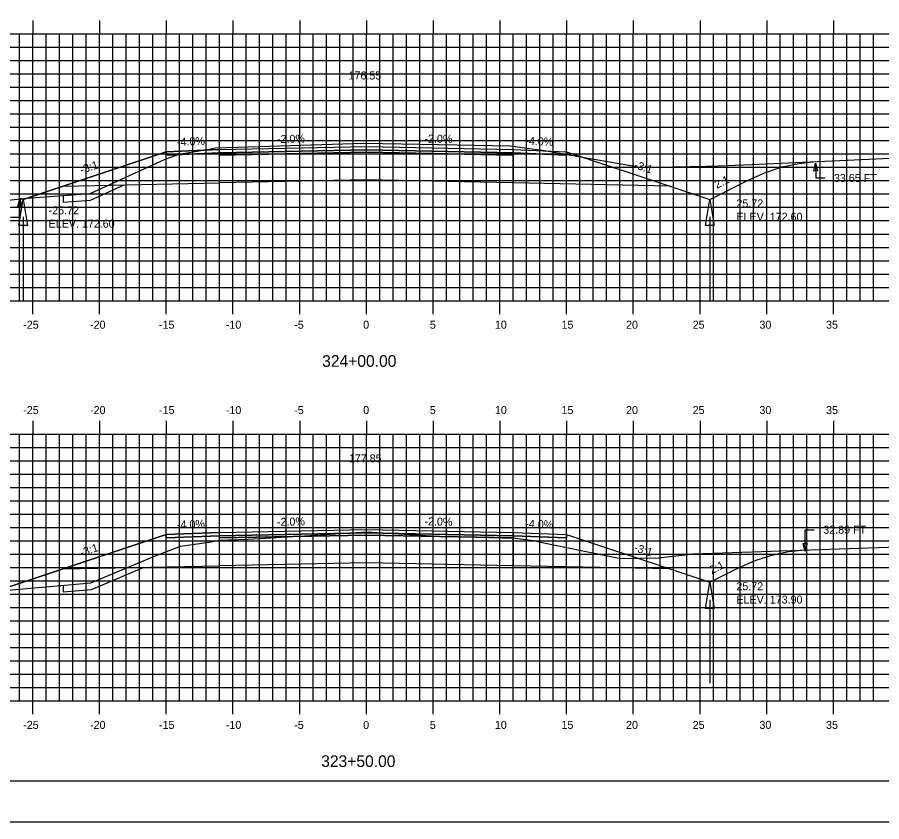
# Model space of a CAD drawing. Extents: x 1140315 to 1140485, y 608981 to 609091.
# Drawn here: x 1140372.3 to 1140437.1, y 608981.3 to 609041.6 of the extents above; entities that cross this region are included whole.
import ezdxf

# ---------------------------------------------------------------- set-up
doc = ezdxf.new("R2010")
doc.units = 0
for name, color, linetype in [('ANNOTATION', 7, 'Continuous'), ('BORDER', 7, 'Continuous'), ('D_Drainage_Ditch_Line', 7, 'Continuous'), ('D_Roadway_Centerline', 7, 'Continuous'), ('D_Roadway_Centerline_Text', 7, 'Continuous'), ('D_Roadway_Edge_Shoulder', 7, 'Continuous'), ('D_Roadway_Edge_TW', 7, 'Continuous'), ('D_Roadway_Pavement', 7, 'Continuous'), ('D_Roadway_SlopeLines', 7, 'Continuous'), ('D_Roadway_SubGrade', 7, 'Continuous'), ('D_Text_Standard', 7, 'Continuous'), ('H_V ANNOTATION', 7, 'Continuous'), ('MAJOR', 7, 'Continuous'), ('MINOR', 7, 'Continuous'), ('PLOT BOUNDARY', 7, 'Continuous'), ('S_Roadway_Centerline', 7, 'Continuous')]:
    doc.layers.add(name, color=color, linetype=linetype)

msp = doc.modelspace()

# ---------------------------------------------------------------- linework, layer by layer
for points in [[(1140372.532, 609027.976), (1140372.59, 609027.978), (1140372.648, 609027.971), (1140372.706, 609027.956), (1140372.763, 609027.931), (1140375.763, 609028.931), (1140383.487, 609031.506), (1140383.488, 609031.506), (1140387.488, 609031.666), (1140398.488, 609031.886), (1140409.488, 609031.666), (1140413.488, 609031.506), (1140421.211, 609028.931), (1140424.211, 609027.931), (1140427.134, 609029.392), (1140428.384, 609029.947), (1140429.634, 609030.359), (1140430.884, 609030.63), (1140432.134, 609030.759)], [(1140370.736, 608998.555), (1140372.763, 608999.23), (1140375.763, 609000.23), (1140383.487, 609002.805), (1140383.488, 609002.805), (1140387.488, 609002.965), (1140398.488, 609003.185), (1140409.488, 609002.965), (1140413.488, 609002.805), (1140421.211, 609000.23), (1140424.211, 608999.23), (1140426.373, 609000.311), (1140427.623, 609000.863), (1140428.873, 609001.27), (1140430.123, 609001.531), (1140431.373, 609001.646)]]:
    msp.add_lwpolyline(points)
at = {"layer": 'BORDER'}
msp.add_lwpolyline([(1140323.488, 608984.335), (1140483.488, 608984.335), (1140483.488, 609089.335), (1140323.488, 609089.335)], close=True, dxfattribs=at)
at = {"layer": 'D_Drainage_Ditch_Line'}
for p, q in [((1140372.763, 609026.619), (1140372.763, 609020.375)), ((1140424.212, 609026.619), (1140424.211, 609020.375)), ((1140424.212, 608997.918), (1140424.211, 608991.675))]:
    msp.add_line(p, q, dxfattribs=at)
for points in [[(1140373.091, 609025.963), (1140372.435, 609025.963), (1140372.763, 609027.931)], [(1140424.54, 609025.963), (1140423.883, 609025.963), (1140424.211, 609027.931)], [(1140424.54, 608997.262), (1140423.883, 608997.262), (1140424.211, 608999.23)]]:
    msp.add_lwpolyline(points, close=True, dxfattribs=at)
at = {"layer": 'D_Roadway_Edge_Shoulder'}
for points in [[(1140387.488, 609031.666), (1140383.488, 609031.506), (1140383.488, 609031.256), (1140387.488, 609031.416)], [(1140409.488, 609031.666), (1140413.488, 609031.506), (1140413.488, 609031.256), (1140409.488, 609031.416)], [(1140387.488, 609002.965), (1140383.488, 609002.805), (1140383.488, 609002.555), (1140387.488, 609002.715)], [(1140409.488, 609002.965), (1140413.488, 609002.805), (1140413.488, 609002.555), (1140409.488, 609002.715)]]:
    msp.add_lwpolyline(points, close=True, dxfattribs=at)
at = {"layer": 'D_Roadway_Edge_TW'}
for points in [[(1140387.488, 609031.416), (1140387.488, 609031.666), (1140398.488, 609031.886), (1140409.488, 609031.666), (1140409.488, 609031.416), (1140398.488, 609031.636)], [(1140387.488, 609002.715), (1140387.488, 609002.965), (1140398.488, 609003.185), (1140409.488, 609002.965), (1140409.488, 609002.715), (1140398.488, 609002.935)]]:
    msp.add_lwpolyline(points, close=True, dxfattribs=at)
at = {"layer": 'D_Roadway_Pavement'}
for points in [[(1140387.488, 609031.249), (1140387.488, 609031.416), (1140398.488, 609031.636), (1140409.488, 609031.416), (1140409.488, 609031.249), (1140398.488, 609031.469)], [(1140387.488, 609002.548), (1140387.488, 609002.715), (1140398.488, 609002.935), (1140409.488, 609002.715), (1140409.488, 609002.548), (1140398.488, 609002.768)]]:
    msp.add_lwpolyline(points, close=True, dxfattribs=at)
at = {"layer": 'D_Roadway_SlopeLines'}
for points in [[(1140424.211, 609027.931), (1140427.134, 609029.392), (1140428.384, 609029.947), (1140429.634, 609030.359), (1140430.884, 609030.63), (1140432.134, 609030.759)], [(1140375.763, 609028.931), (1140372.763, 609027.931)], [(1140375.763, 609028.228), (1140375.763, 609027.728), (1140377.819, 609027.877), (1140380.328, 609029.022)], [(1140421.211, 609028.931), (1140424.211, 609027.931)], [(1140372.763, 609027.931), (1140372.706, 609027.956), (1140372.648, 609027.971), (1140372.59, 609027.978), (1140372.532, 609027.976)], [(1140424.211, 608999.23), (1140426.373, 609000.311), (1140427.623, 609000.863), (1140428.873, 609001.27), (1140430.123, 609001.531), (1140431.373, 609001.646)], [(1140375.763, 609000.23), (1140372.763, 608999.23)], [(1140375.763, 608998.999), (1140375.763, 608998.499), (1140377.894, 608998.688), (1140381.835, 609000.352)], [(1140421.211, 609000.23), (1140424.211, 608999.23)], [(1140372.763, 608999.23), (1140370.736, 608998.555)]]:
    msp.add_lwpolyline(points, dxfattribs=at)
at = {"layer": 'D_Roadway_SubGrade'}
for points in [[(1140387.488, 609031.249), (1140387.488, 609031.416), (1140383.488, 609031.256), (1140383.488, 609031.506), (1140383.487, 609031.506), (1140375.763, 609028.931), (1140387.488, 609029.166)], [(1140409.488, 609031.249), (1140409.488, 609031.416), (1140413.488, 609031.256), (1140413.488, 609031.506), (1140413.488, 609031.506), (1140421.211, 609028.931), (1140409.488, 609029.166)], [(1140387.488, 609029.166), (1140387.488, 609031.249), (1140398.488, 609031.469), (1140409.488, 609031.249), (1140409.488, 609029.166), (1140398.488, 609029.386)], [(1140387.488, 609002.548), (1140387.488, 609002.715), (1140383.488, 609002.555), (1140383.488, 609002.805), (1140383.487, 609002.805), (1140375.763, 609000.23), (1140387.488, 609000.465)], [(1140387.488, 609000.465), (1140387.488, 609002.548), (1140398.488, 609002.768), (1140409.488, 609002.548), (1140409.488, 609000.465), (1140398.488, 609000.685)], [(1140409.488, 609002.548), (1140409.488, 609002.715), (1140413.488, 609002.555), (1140413.488, 609002.805), (1140413.488, 609002.805), (1140421.211, 609000.23), (1140409.488, 609000.465)]]:
    msp.add_lwpolyline(points, close=True, dxfattribs=at)
at = {"layer": 'D_Text_Standard'}
for points in [[(1140432.134, 609030.642), (1140432.292, 609030.063), (1140432.001, 609030.057)], [(1140372.532, 609027.976), (1140372.665, 609027.391), (1140372.374, 609027.397)], [(1140431.373, 609001.561), (1140431.223, 609002.142), (1140431.514, 609002.145)]]:
    msp.add_lwpolyline(points, close=True, dxfattribs=at)
for points in [[(1140432.134, 609030.642), (1140432.157, 609029.535), (1140432.837, 609029.535)], [(1140372.532, 609027.976), (1140372.501, 609026.568), (1140371.821, 609026.568)], [(1140431.373, 609001.561), (1140431.36, 609003.165), (1140432.04, 609003.165)]]:
    msp.add_lwpolyline(points, dxfattribs=at)
at = {"layer": 'MAJOR'}
for p, q in [((1140373.488, 609041.337), (1140373.488, 609040.335)), ((1140378.488, 609041.337), (1140378.488, 609040.335)), ((1140383.488, 609041.337), (1140383.488, 609040.335)), ((1140388.488, 609041.337), (1140388.488, 609040.335)), ((1140393.488, 609041.337), (1140393.488, 609040.335)), ((1140398.488, 609041.337), (1140398.488, 609040.335)), ((1140403.488, 609041.337), (1140403.488, 609040.335)), ((1140408.488, 609041.337), (1140408.488, 609040.335)), ((1140413.488, 609041.337), (1140413.488, 609040.335)), ((1140418.488, 609041.337), (1140418.488, 609040.335)), ((1140423.488, 609041.337), (1140423.488, 609040.335)), ((1140428.488, 609041.337), (1140428.488, 609040.335)), ((1140433.488, 609041.337), (1140433.488, 609040.335)), ((1140328.488, 609040.335), (1140468.488, 609040.335)), ((1140328.488, 609040.335), (1140468.488, 609040.335)), ((1140373.488, 609020.335), (1140373.488, 609040.335)), ((1140378.488, 609020.335), (1140378.488, 609040.335)), ((1140383.488, 609020.335), (1140383.488, 609040.335)), ((1140388.488, 609020.335), (1140388.488, 609040.335)), ((1140393.488, 609020.335), (1140393.488, 609040.335)), ((1140398.488, 609020.335), (1140398.488, 609040.335)), ((1140403.488, 609020.335), (1140403.488, 609040.335)), ((1140408.488, 609020.335), (1140408.488, 609040.335)), ((1140413.488, 609020.335), (1140413.488, 609040.335)), ((1140418.488, 609020.335), (1140418.488, 609040.335)), ((1140423.488, 609020.335), (1140423.488, 609040.335)), ((1140428.488, 609020.335), (1140428.488, 609040.335)), ((1140433.488, 609020.335), (1140433.488, 609040.335)), ((1140328.488, 609035.335), (1140468.488, 609035.335)), ((1140328.488, 609030.335), (1140468.488, 609030.335)), ((1140328.488, 609025.335), (1140468.488, 609025.335)), ((1140328.488, 609020.335), (1140468.488, 609020.335)), ((1140328.488, 609020.335), (1140468.488, 609020.335)), ((1140373.488, 609019.333), (1140373.488, 609020.335)), ((1140378.488, 609019.333), (1140378.488, 609020.335)), ((1140383.488, 609019.333), (1140383.488, 609020.335)), ((1140388.488, 609019.333), (1140388.488, 609020.335)), ((1140393.488, 609019.333), (1140393.488, 609020.335)), ((1140398.488, 609019.333), (1140398.488, 609020.335)), ((1140403.488, 609019.333), (1140403.488, 609020.335)), ((1140408.488, 609019.333), (1140408.488, 609020.335)), ((1140413.488, 609019.333), (1140413.488, 609020.335)), ((1140418.488, 609019.333), (1140418.488, 609020.335)), ((1140423.488, 609019.333), (1140423.488, 609020.335)), ((1140428.488, 609019.333), (1140428.488, 609020.335)), ((1140433.488, 609019.333), (1140433.488, 609020.335)), ((1140373.488, 609011.337), (1140373.488, 609010.335)), ((1140378.488, 609011.337), (1140378.488, 609010.335)), ((1140383.488, 609011.337), (1140383.488, 609010.335)), ((1140388.488, 609011.337), (1140388.488, 609010.335)), ((1140393.488, 609011.337), (1140393.488, 609010.335)), ((1140398.488, 609011.337), (1140398.488, 609010.335)), ((1140403.488, 609011.337), (1140403.488, 609010.335)), ((1140408.488, 609011.337), (1140408.488, 609010.335)), ((1140413.488, 609011.337), (1140413.488, 609010.335)), ((1140418.488, 609011.337), (1140418.488, 609010.335)), ((1140423.488, 609011.337), (1140423.488, 609010.335)), ((1140428.488, 609011.337), (1140428.488, 609010.335)), ((1140433.488, 609011.337), (1140433.488, 609010.335)), ((1140328.488, 609010.335), (1140468.488, 609010.335)), ((1140328.488, 609010.335), (1140468.488, 609010.335)), ((1140373.488, 608990.335), (1140373.488, 609010.335)), ((1140378.488, 608990.335), (1140378.488, 609010.335)), ((1140383.488, 608990.335), (1140383.488, 609010.335)), ((1140388.488, 608990.335), (1140388.488, 609010.335)), ((1140393.488, 608990.335), (1140393.488, 609010.335)), ((1140398.488, 608990.335), (1140398.488, 609010.335)), ((1140403.488, 608990.335), (1140403.488, 609010.335)), ((1140408.488, 608990.335), (1140408.488, 609010.335)), ((1140413.488, 608990.335), (1140413.488, 609010.335)), ((1140418.488, 608990.335), (1140418.488, 609010.335)), ((1140423.488, 608990.335), (1140423.488, 609010.335)), ((1140428.488, 608990.335), (1140428.488, 609010.335)), ((1140433.488, 608990.335), (1140433.488, 609010.335)), ((1140328.488, 609005.335), (1140468.488, 609005.335)), ((1140328.488, 609000.335), (1140468.488, 609000.335)), ((1140328.488, 608995.335), (1140468.488, 608995.335)), ((1140328.488, 608990.335), (1140468.488, 608990.335)), ((1140328.488, 608990.335), (1140468.488, 608990.335)), ((1140373.488, 608989.333), (1140373.488, 608990.335)), ((1140378.488, 608989.333), (1140378.488, 608990.335)), ((1140383.488, 608989.333), (1140383.488, 608990.335)), ((1140388.488, 608989.333), (1140388.488, 608990.335)), ((1140393.488, 608989.333), (1140393.488, 608990.335)), ((1140398.488, 608989.333), (1140398.488, 608990.335)), ((1140403.488, 608989.333), (1140403.488, 608990.335)), ((1140408.488, 608989.333), (1140408.488, 608990.335)), ((1140413.488, 608989.333), (1140413.488, 608990.335)), ((1140418.488, 608989.333), (1140418.488, 608990.335)), ((1140423.488, 608989.333), (1140423.488, 608990.335)), ((1140428.488, 608989.333), (1140428.488, 608990.335)), ((1140433.488, 608989.333), (1140433.488, 608990.335))]:
    msp.add_line(p, q, dxfattribs=at)
at = {"layer": 'MINOR'}
for p, q in [((1140372.488, 609020.335), (1140372.488, 609040.335)), ((1140374.488, 609020.335), (1140374.488, 609040.335)), ((1140375.488, 609020.335), (1140375.488, 609040.335)), ((1140376.488, 609020.335), (1140376.488, 609040.335)), ((1140377.488, 609020.335), (1140377.488, 609040.335)), ((1140379.488, 609020.335), (1140379.488, 609040.335)), ((1140380.488, 609020.335), (1140380.488, 609040.335)), ((1140381.488, 609020.335), (1140381.488, 609040.335)), ((1140382.488, 609020.335), (1140382.488, 609040.335)), ((1140384.488, 609020.335), (1140384.488, 609040.335)), ((1140385.488, 609020.335), (1140385.488, 609040.335)), ((1140386.488, 609020.335), (1140386.488, 609040.335)), ((1140387.488, 609020.335), (1140387.488, 609040.335)), ((1140389.488, 609020.335), (1140389.488, 609040.335)), ((1140390.488, 609020.335), (1140390.488, 609040.335)), ((1140391.488, 609020.335), (1140391.488, 609040.335)), ((1140392.488, 609020.335), (1140392.488, 609040.335)), ((1140394.488, 609020.335), (1140394.488, 609040.335)), ((1140395.488, 609020.335), (1140395.488, 609040.335)), ((1140396.488, 609020.335), (1140396.488, 609040.335)), ((1140397.488, 609020.335), (1140397.488, 609040.335)), ((1140399.488, 609020.335), (1140399.488, 609040.335)), ((1140400.488, 609020.335), (1140400.488, 609040.335)), ((1140401.488, 609020.335), (1140401.488, 609040.335)), ((1140402.488, 609020.335), (1140402.488, 609040.335)), ((1140404.488, 609020.335), (1140404.488, 609040.335)), ((1140405.488, 609020.335), (1140405.488, 609040.335)), ((1140406.488, 609020.335), (1140406.488, 609040.335)), ((1140407.488, 609020.335), (1140407.488, 609040.335)), ((1140409.488, 609020.335), (1140409.488, 609040.335)), ((1140410.488, 609020.335), (1140410.488, 609040.335)), ((1140411.488, 609020.335), (1140411.488, 609040.335)), ((1140412.488, 609020.335), (1140412.488, 609040.335)), ((1140414.488, 609020.335), (1140414.488, 609040.335)), ((1140415.488, 609020.335), (1140415.488, 609040.335)), ((1140416.488, 609020.335), (1140416.488, 609040.335)), ((1140417.488, 609020.335), (1140417.488, 609040.335)), ((1140419.488, 609020.335), (1140419.488, 609040.335)), ((1140420.488, 609020.335), (1140420.488, 609040.335)), ((1140421.488, 609020.335), (1140421.488, 609040.335)), ((1140422.488, 609020.335), (1140422.488, 609040.335)), ((1140424.488, 609020.335), (1140424.488, 609040.335)), ((1140425.488, 609020.335), (1140425.488, 609040.335)), ((1140426.488, 609020.335), (1140426.488, 609040.335)), ((1140427.488, 609020.335), (1140427.488, 609040.335)), ((1140429.488, 609020.335), (1140429.488, 609040.335)), ((1140430.488, 609020.335), (1140430.488, 609040.335)), ((1140431.488, 609020.335), (1140431.488, 609040.335)), ((1140432.488, 609020.335), (1140432.488, 609040.335)), ((1140434.488, 609020.335), (1140434.488, 609040.335)), ((1140435.488, 609020.335), (1140435.488, 609040.335)), ((1140436.488, 609020.335), (1140436.488, 609040.335)), ((1140328.488, 609039.335), (1140468.488, 609039.335)), ((1140328.488, 609038.335), (1140468.488, 609038.335)), ((1140328.488, 609037.335), (1140468.488, 609037.335)), ((1140328.488, 609036.335), (1140468.488, 609036.335)), ((1140328.488, 609034.335), (1140468.488, 609034.335)), ((1140328.488, 609033.335), (1140468.488, 609033.335)), ((1140328.488, 609032.335), (1140468.488, 609032.335)), ((1140328.488, 609031.335), (1140468.488, 609031.335)), ((1140328.488, 609029.335), (1140468.488, 609029.335)), ((1140328.488, 609028.335), (1140468.488, 609028.335)), ((1140328.488, 609027.335), (1140468.488, 609027.335)), ((1140328.488, 609026.335), (1140468.488, 609026.335)), ((1140328.488, 609024.335), (1140468.488, 609024.335)), ((1140328.488, 609023.335), (1140468.488, 609023.335)), ((1140328.488, 609022.335), (1140468.488, 609022.335)), ((1140328.488, 609021.335), (1140468.488, 609021.335)), ((1140372.488, 608990.335), (1140372.488, 609010.335)), ((1140374.488, 608990.335), (1140374.488, 609010.335)), ((1140375.488, 608990.335), (1140375.488, 609010.335)), ((1140376.488, 608990.335), (1140376.488, 609010.335)), ((1140377.488, 608990.335), (1140377.488, 609010.335)), ((1140379.488, 608990.335), (1140379.488, 609010.335)), ((1140380.488, 608990.335), (1140380.488, 609010.335)), ((1140381.488, 608990.335), (1140381.488, 609010.335)), ((1140382.488, 608990.335), (1140382.488, 609010.335)), ((1140384.488, 608990.335), (1140384.488, 609010.335)), ((1140385.488, 608990.335), (1140385.488, 609010.335)), ((1140386.488, 608990.335), (1140386.488, 609010.335)), ((1140387.488, 608990.335), (1140387.488, 609010.335)), ((1140389.488, 608990.335), (1140389.488, 609010.335)), ((1140390.488, 608990.335), (1140390.488, 609010.335)), ((1140391.488, 608990.335), (1140391.488, 609010.335)), ((1140392.488, 608990.335), (1140392.488, 609010.335)), ((1140394.488, 608990.335), (1140394.488, 609010.335)), ((1140395.488, 608990.335), (1140395.488, 609010.335)), ((1140396.488, 608990.335), (1140396.488, 609010.335)), ((1140397.488, 608990.335), (1140397.488, 609010.335)), ((1140399.488, 608990.335), (1140399.488, 609010.335)), ((1140400.488, 608990.335), (1140400.488, 609010.335)), ((1140401.488, 608990.335), (1140401.488, 609010.335)), ((1140402.488, 608990.335), (1140402.488, 609010.335)), ((1140404.488, 608990.335), (1140404.488, 609010.335)), ((1140405.488, 608990.335), (1140405.488, 609010.335)), ((1140406.488, 608990.335), (1140406.488, 609010.335)), ((1140407.488, 608990.335), (1140407.488, 609010.335)), ((1140409.488, 608990.335), (1140409.488, 609010.335)), ((1140410.488, 608990.335), (1140410.488, 609010.335)), ((1140411.488, 608990.335), (1140411.488, 609010.335)), ((1140412.488, 608990.335), (1140412.488, 609010.335)), ((1140414.488, 608990.335), (1140414.488, 609010.335)), ((1140415.488, 608990.335), (1140415.488, 609010.335)), ((1140416.488, 608990.335), (1140416.488, 609010.335)), ((1140417.488, 608990.335), (1140417.488, 609010.335)), ((1140419.488, 608990.335), (1140419.488, 609010.335)), ((1140420.488, 608990.335), (1140420.488, 609010.335)), ((1140421.488, 608990.335), (1140421.488, 609010.335)), ((1140422.488, 608990.335), (1140422.488, 609010.335)), ((1140424.488, 608990.335), (1140424.488, 609010.335)), ((1140425.488, 608990.335), (1140425.488, 609010.335)), ((1140426.488, 608990.335), (1140426.488, 609010.335)), ((1140427.488, 608990.335), (1140427.488, 609010.335)), ((1140429.488, 608990.335), (1140429.488, 609010.335)), ((1140430.488, 608990.335), (1140430.488, 609010.335)), ((1140431.488, 608990.335), (1140431.488, 609010.335)), ((1140432.488, 608990.335), (1140432.488, 609010.335)), ((1140434.488, 608990.335), (1140434.488, 609010.335)), ((1140435.488, 608990.335), (1140435.488, 609010.335)), ((1140436.488, 608990.335), (1140436.488, 609010.335)), ((1140328.488, 609009.335), (1140468.488, 609009.335)), ((1140328.488, 609008.335), (1140468.488, 609008.335)), ((1140328.488, 609007.335), (1140468.488, 609007.335)), ((1140328.488, 609006.335), (1140468.488, 609006.335)), ((1140328.488, 609004.335), (1140468.488, 609004.335)), ((1140328.488, 609003.335), (1140468.488, 609003.335)), ((1140328.488, 609002.335), (1140468.488, 609002.335)), ((1140328.488, 609001.335), (1140468.488, 609001.335)), ((1140328.488, 608999.335), (1140468.488, 608999.335)), ((1140328.488, 608998.335), (1140468.488, 608998.335)), ((1140328.488, 608997.335), (1140468.488, 608997.335)), ((1140328.488, 608996.335), (1140468.488, 608996.335)), ((1140328.488, 608994.335), (1140468.488, 608994.335)), ((1140328.488, 608993.335), (1140468.488, 608993.335)), ((1140328.488, 608992.335), (1140468.488, 608992.335)), ((1140328.488, 608991.335), (1140468.488, 608991.335))]:
    msp.add_line(p, q, dxfattribs=at)
at = {"layer": 'PLOT BOUNDARY'}
msp.add_lwpolyline([(1140315.395, 608981.276), (1140485.395, 608981.276), (1140485.395, 609091.276), (1140315.395, 609091.276)], close=True, dxfattribs=at)
at = {"layer": 'S_Roadway_Centerline'}
for points in [[(1140363.42, 609026.944), (1140373.015, 609028.03), (1140377.783, 609028.374), (1140383.357, 609030.919), (1140384.446, 609031.317), (1140386.704, 609031.7), (1140387.162, 609031.789), (1140388.836, 609031.847), (1140398.293, 609032.157), (1140403.918, 609032.055), (1140409.283, 609031.936), (1140410.508, 609031.768), (1140411.694, 609031.611), (1140418.287, 609030.462), (1140419.066, 609030.326), (1140423.927, 609030.429), (1140424.22, 609030.421), (1140427.364, 609030.537), (1140450.895, 609031.63), (1140457.789, 609031.917), (1140468.488, 609032.187)], [(1140367.542, 608998.327), (1140370.795, 608998.559), (1140377.85, 608999.184), (1140382.728, 609001.243), (1140384.55, 609001.921), (1140386.861, 609002.265), (1140387.461, 609002.383), (1140389.636, 609002.458), (1140393.842, 609002.696), (1140398.506, 609003.008), (1140403.767, 609002.674), (1140409.646, 609002.543), (1140411.009, 609002.36), (1140411.793, 609002.182), (1140414.446, 609001.638), (1140417.551, 609001.002), (1140420.367, 609001.06), (1140422.978, 609001.362), (1140440.501, 609001.955), (1140446.381, 609002.087), (1140464.846, 609002.691), (1140468.488, 609002.74)]]:
    msp.add_lwpolyline(points, dxfattribs=at)

# ---------------------------------------------------------------- texts
at = {"layer": 'ANNOTATION'}
for s, rotation, p in [('-2.0%', 1.14576, (1140391.791, 609032.152)), ('-2.0%', 358.85424, (1140402.831, 609032.199)), ('-4.0%', 2.29061, (1140384.304, 609031.939)), ('-4.0%', 357.70939, (1140410.384, 609032.031)), ('-3:1', 18.43482, (1140377.142, 609029.845)), ('-3:1', 341.56521, (1140418.499, 609030.289)), ('2:1', 26.56505, (1140424.745, 609028.716)), ('-4.0%', 2.29061, (1140384.304, 609003.238)), ('-2.0%', 1.14576, (1140391.791, 609003.451)), ('-2.0%', 358.85424, (1140402.831, 609003.498)), ('-4.0%', 357.70939, (1140410.384, 609003.33)), ('-3:1', 18.43482, (1140377.142, 609001.144)), ('-3:1', 341.56521, (1140418.499, 609001.588)), ('2:1', 26.56505, (1140424.365, 608999.825))]:
    msp.add_text(s, height=0.6, rotation=rotation, dxfattribs=at).set_placement(p)
at = {"layer": 'D_Roadway_Centerline'}
for s, p in [('C', (1140398.483, 609031.886)), ('L', (1140398.488, 609031.878)), ('C', (1140398.483, 609003.185)), ('L', (1140398.488, 609003.177))]:
    msp.add_text(s, height=0.0146, dxfattribs=at).set_placement(p)
at = {"layer": 'D_Roadway_Centerline_Text'}
for s, p in [('176.55', (1140397.147, 609036.918)), ('177.85', (1140397.174, 609008.217))]:
    msp.add_text(s, height=0.6, dxfattribs=at).set_placement(p)
at = {"layer": 'D_Text_Standard'}
for s, p in [('33.65 FT', (1140433.517, 609029.235)), ('25.72', (1140426.212, 609027.331)), ('-25.72', (1140374.675, 609026.811)), ('ELEV. 172.60', (1140374.675, 609025.809)), ('ELEV. 172.60', (1140426.212, 609026.329)), ('32.89 FT', (1140432.72, 609002.865)), ('25.72', (1140426.212, 608998.63)), ('ELEV. 173.90', (1140426.212, 608997.628))]:
    msp.add_text(s, height=0.6, dxfattribs=at).set_placement(p)
at = {"layer": 'H_V ANNOTATION'}
for s, height, p in [('-25', 0.6, (1140372.773, 609018.235)), ('-20', 0.6, (1140377.781, 609018.235)), ('-15', 0.6, (1140382.945, 609018.235)), ('-10', 0.6, (1140387.953, 609018.235)), ('-5', 0.6, (1140393.079, 609018.235)), ('0', 0.6, (1140398.247, 609018.235)), ('5', 0.6, (1140403.239, 609018.235)), ('10', 0.6, (1140408.113, 609018.235)), ('15', 0.6, (1140413.105, 609018.235)), ('20', 0.6, (1140417.942, 609018.235)), ('25', 0.6, (1140422.934, 609018.235)), ('30', 0.6, (1140427.937, 609018.235)), ('35', 0.6, (1140432.929, 609018.235)), ('324+00.00', 0.875, (1140395.172, 609015.378)), ('-25', 0.6, (1140372.773, 609011.835)), ('-20', 0.6, (1140377.781, 609011.835)), ('-15', 0.6, (1140382.945, 609011.835)), ('-10', 0.6, (1140387.953, 609011.835)), ('-5', 0.6, (1140393.079, 609011.835)), ('0', 0.6, (1140398.247, 609011.835)), ('5', 0.6, (1140403.239, 609011.835)), ('10', 0.6, (1140408.113, 609011.835)), ('15', 0.6, (1140413.105, 609011.835)), ('20', 0.6, (1140417.942, 609011.835)), ('25', 0.6, (1140422.934, 609011.835)), ('30', 0.6, (1140427.937, 609011.835)), ('35', 0.6, (1140432.929, 609011.835)), ('-25', 0.6, (1140372.773, 608988.235)), ('-20', 0.6, (1140377.781, 608988.235)), ('-15', 0.6, (1140382.945, 608988.235)), ('-10', 0.6, (1140387.953, 608988.235)), ('-5', 0.6, (1140393.079, 608988.235)), ('0', 0.6, (1140398.247, 608988.235)), ('5', 0.6, (1140403.239, 608988.235)), ('10', 0.6, (1140408.113, 608988.235)), ('15', 0.6, (1140413.105, 608988.235)), ('20', 0.6, (1140417.942, 608988.235)), ('25', 0.6, (1140422.934, 608988.235)), ('30', 0.6, (1140427.937, 608988.235)), ('35', 0.6, (1140432.929, 608988.235)), ('323+50.00', 0.875, (1140395.101, 608985.378))]:
    msp.add_text(s, height=height, dxfattribs=at).set_placement(p)
at = {"layer": 'S_Roadway_Centerline'}
for s, p in [('L', (1140398.285, 609032.15)), ('C', (1140398.288, 609032.157)), ('C', (1140398.501, 609003.008)), ('L', (1140398.506, 609003.001))]:
    msp.add_text(s, height=0.0146, dxfattribs=at).set_placement(p)

doc.saveas('drawing.dxf')
